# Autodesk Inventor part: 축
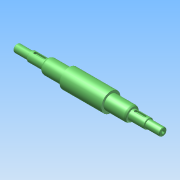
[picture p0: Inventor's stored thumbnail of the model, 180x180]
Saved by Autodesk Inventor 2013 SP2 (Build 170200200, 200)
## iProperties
Created: 2025-10
Part Number: 축
Material: Generic
Document SubType Name: Modeling
Designer: 601
Density: 1 g/cm^3
변환 표준: STEP AP214IS
전처리기: Build: 200, Release: 2013 SP2 Update 6 - Date: Thu 07/17/2014
전송 단위: 밀리미터
불확실성: 0.01
Author: 601
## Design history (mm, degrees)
node "축1"
node "솔리드1"
node "기준1"
